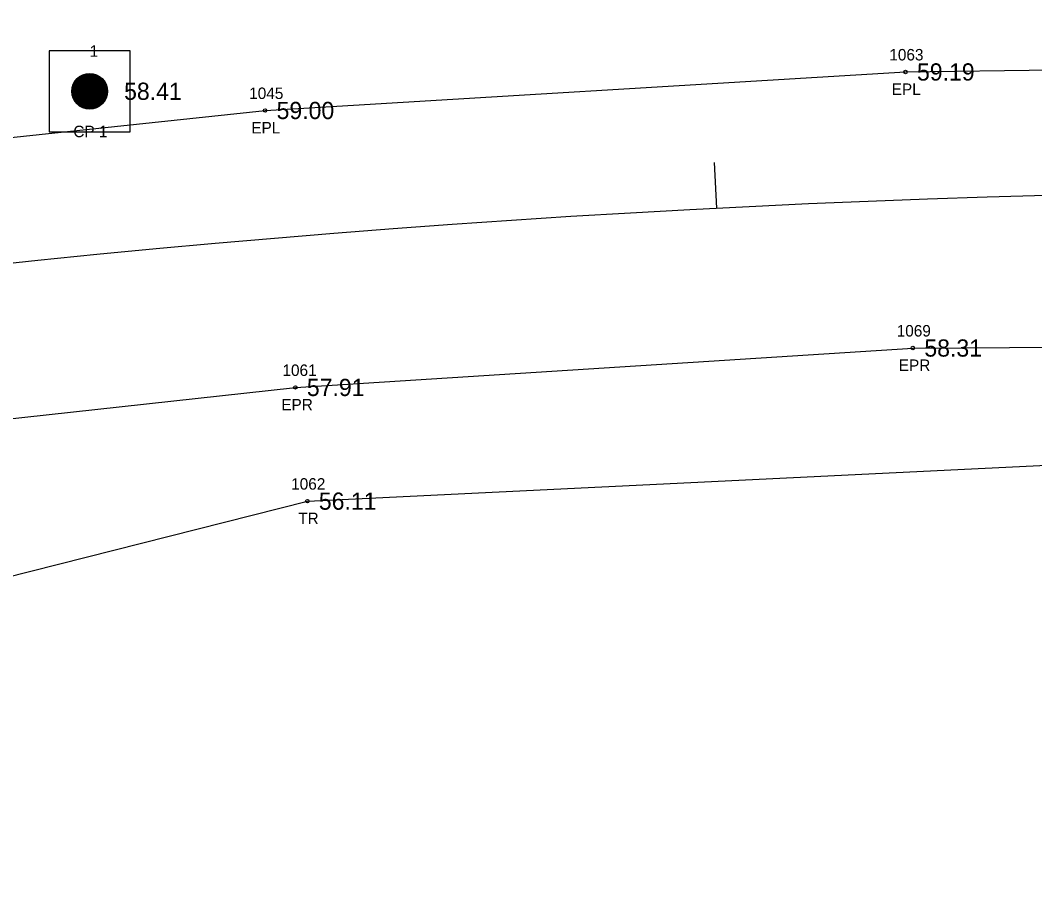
# Model space of a CAD drawing. Extents: x 2420113 to 2422887, y 845323 to 846653.
# Drawn here: x 2420530 to 2420618.3, y 845663.8 to 845739.4 of the extents above; entities that cross this region are included whole.
import ezdxf

# ---------------------------------------------------------------- set-up
doc = ezdxf.new("R2010")
doc.units = 0
for name, color, linetype in [('RD_EX_Road', 7, 'Continuous'), ('RD_EX_Road_txCode', 7, 'Continuous'), ('RD_EX_TX_Road_ELEV', 7, 'Continuous'), ('RD_EX_TX_VEG_ELEV', 7, 'Continuous'), ('RD_EX_VEG', 7, 'Continuous'), ('RD_EX_VEG_txCode', 7, 'Continuous'), ('RD_HC_Cl', 7, 'Continuous'), ('RD_HC_Data_Tic', 7, 'Continuous'), ('RD_HC_Survey', 7, 'Continuous'), ('RD_HC_Survey_ELEV', 7, 'Continuous'), ('RD_HC_Survey_txCode', 7, 'Continuous'), ('RD_SMD_Locator', 7, 'Continuous')]:
    doc.layers.add(name, color=color, linetype=linetype)

msp = doc.modelspace()

# ---------------------------------------------------------------- linework, layer by layer
at = {"layer": 'RD_EX_Road'}
for points in [[(2420388.282, 845680.385), (2420441.289, 845692.044), (2420492.621, 845700.703), (2420553.92, 845707.412), (2420607.692, 845710.846), (2420682.38, 845711.255), (2420749.444, 845707.273), (2420795.122, 845703.444), (2420900.283, 845693.42), (2421017.167, 845682.19), (2421113.896, 845672.969), (2421174.872, 845668.158), (2421234.589, 845666.133), (2421293.003, 845667.248), (2421351.244, 845671.501), (2421419.818, 845681.166), (2421463.191, 845688.629), (2421558.819, 845713.183), (2421614.573, 845730.452), (2421670.73, 845751.42), (2421735.61, 845780.497), (2421750.751, 845787.871), (2421744.667, 845798.217), (2421739.213, 845808.113)], [(2420376.352, 845701.929), (2420403.683, 845709.109), (2420436.454, 845715.41), (2420465.848, 845720.803), (2420487.585, 845724.764), (2420551.285, 845731.534), (2420607.051, 845734.891), (2420658.723, 845735.587), (2420682.859, 845735.472), (2420736.675, 845732.558), (2420795.395, 845727.646), (2420889.703, 845718.983), (2420911.08, 845716.872), (2420953.907, 845713.711), (2420998.338, 845708.254), (2421018.473, 845706.548), (2421116.022, 845696.98), (2421176.982, 845692.004), (2421235.853, 845690.144), (2421292.319, 845691.436), (2421350.221, 845695.49), (2421412.35, 845704.283)]]:
    msp.add_lwpolyline(points, dxfattribs=at)
at = {"layer": 'RD_EX_VEG'}
msp.add_lwpolyline([(2420391.438, 845659.631), (2420497.123, 845682.866), (2420554.964, 845697.51), (2420665.259, 845702.876), (2420735.635, 845697.654), (2420790.664, 845674.795), (2421018.223, 845655.053), (2421176.125, 845636.219), (2421296.761, 845636.574), (2421411.609, 845653.106), (2421415.242, 845569.551)], dxfattribs=at)
at = {"layer": 'RD_HC_Cl'}
msp.add_arc((2420649.068, 844578.355), 1146.148, 84.464761, 117.648099, dxfattribs=at)
at = {"layer": 'RD_HC_Data_Tic'}
msp.add_line((2420590.62, 845723.012), (2420590.416, 845727.007), dxfattribs=at)
at = {"layer": 'RD_HC_Survey'}
for p, q in [((2420534.794, 845732.234), (2420534.794, 845734.181)), ((2420534.844, 845732.175), (2420534.844, 845734.24)), ((2420534.894, 845732.121), (2420534.894, 845734.294)), ((2420534.944, 845732.072), (2420534.944, 845734.343)), ((2420534.994, 845732.027), (2420534.994, 845734.388)), ((2420535.044, 845731.986), (2420535.044, 845734.429)), ((2420535.094, 845731.949), (2420535.094, 845734.467)), ((2420535.144, 845731.914), (2420535.144, 845734.501)), ((2420535.194, 845731.882), (2420535.194, 845734.533)), ((2420535.244, 845731.853), (2420535.244, 845734.563)), ((2420535.294, 845731.826), (2420535.294, 845734.59)), ((2420535.344, 845731.801), (2420535.344, 845734.614)), ((2420535.394, 845731.778), (2420535.394, 845734.637)), ((2420535.444, 845731.758), (2420535.444, 845734.657)), ((2420535.494, 845731.74), (2420535.494, 845734.675)), ((2420535.544, 845731.723), (2420535.544, 845734.692)), ((2420535.594, 845731.709), (2420535.594, 845734.707)), ((2420535.644, 845731.696), (2420535.644, 845734.719)), ((2420535.694, 845731.685), (2420535.694, 845734.731)), ((2420535.744, 845731.675), (2420535.744, 845734.74)), ((2420535.794, 845731.668), (2420535.794, 845734.748)), ((2420535.844, 845731.661), (2420535.844, 845734.754)), ((2420535.894, 845731.657), (2420535.894, 845734.758)), ((2420535.944, 845731.654), (2420535.944, 845734.761)), ((2420535.994, 845731.653), (2420535.994, 845734.762)), ((2420536.044, 845731.653), (2420536.044, 845734.762)), ((2420536.094, 845731.656), (2420536.094, 845734.76)), ((2420536.144, 845731.659), (2420536.144, 845734.756)), ((2420536.194, 845731.664), (2420536.194, 845734.751)), ((2420536.244, 845731.671), (2420536.244, 845734.744)), ((2420536.294, 845731.68), (2420536.294, 845734.735)), ((2420536.344, 845731.69), (2420536.344, 845734.725)), ((2420536.394, 845731.702), (2420536.394, 845734.713)), ((2420536.444, 845731.716), (2420536.444, 845734.699)), ((2420536.494, 845731.732), (2420536.494, 845734.684)), ((2420536.544, 845731.749), (2420536.544, 845734.666)), ((2420536.594, 845731.769), (2420536.594, 845734.647)), ((2420536.644, 845731.79), (2420536.644, 845734.625)), ((2420536.694, 845731.814), (2420536.694, 845734.602)), ((2420536.744, 845731.839), (2420536.744, 845734.576)), ((2420536.794, 845731.868), (2420536.794, 845734.548)), ((2420536.844, 845731.898), (2420536.844, 845734.517)), ((2420536.894, 845731.932), (2420536.894, 845734.484)), ((2420536.944, 845731.968), (2420536.944, 845734.447)), ((2420536.994, 845732.007), (2420536.994, 845734.408)), ((2420537.044, 845732.05), (2420537.044, 845734.365)), ((2420537.094, 845732.097), (2420537.094, 845734.318)), ((2420537.144, 845732.149), (2420537.144, 845734.267)), ((2420537.194, 845732.205), (2420537.194, 845734.21)), ((2420537.244, 845732.267), (2420537.244, 845734.148)), ((2420534.494, 845732.846), (2420534.494, 845733.569)), ((2420534.544, 845732.679), (2420534.544, 845733.736)), ((2420534.594, 845732.557), (2420534.594, 845733.858)), ((2420534.644, 845732.458), (2420534.644, 845733.957)), ((2420534.694, 845732.374), (2420534.694, 845734.042)), ((2420534.744, 845732.3), (2420534.744, 845734.116)), ((2420537.294, 845732.337), (2420537.294, 845734.078)), ((2420537.344, 845732.416), (2420537.344, 845733.999)), ((2420537.394, 845732.508), (2420537.394, 845733.908)), ((2420537.444, 845732.617), (2420537.444, 845733.798)), ((2420537.494, 845732.758), (2420537.494, 845733.657)), ((2420537.544, 845732.982), (2420537.544, 845733.433))]:
    msp.add_line(p, q, dxfattribs=at)
msp.add_lwpolyline([(2420539.541, 845736.743), (2420532.47, 845736.743), (2420532.47, 845729.672), (2420539.541, 845729.672)], close=True, dxfattribs=at)
msp.add_circle((2420536.006, 845733.208), 1.555, dxfattribs=at)
at = {"layer": 'RD_SMD_Locator'}
for centre in [(2420607.051, 845734.891), (2420536.006, 845733.208), (2420551.285, 845731.534), (2420607.692, 845710.846), (2420553.92, 845707.412), (2420554.964, 845697.51)]:
    msp.add_circle(centre, 0.15, dxfattribs=at)

# ---------------------------------------------------------------- texts
at = {"layer": 'RD_EX_Road_txCode'}
for s, p in [('1063', (2420605.641, 845735.891)), ('1045', (2420549.899, 845732.534)), ('EPL', (2420605.846, 845732.891)), ('EPL', (2420550.081, 845729.534)), ('1069', (2420606.283, 845711.846)), ('1061', (2420552.794, 845708.412)), ('EPR', (2420606.464, 845708.846)), ('EPR', (2420552.692, 845705.412))]:
    msp.add_text(s, height=1, dxfattribs=at).set_placement(p)
at = {"layer": 'RD_EX_TX_Road_ELEV'}
for s, p in [('59.19', (2420608.051, 845734.141)), ('59.00', (2420552.285, 845730.784)), ('58.31', (2420608.692, 845710.096)), ('57.91', (2420554.92, 845706.662))]:
    msp.add_text(s, height=1.5, dxfattribs=at).set_placement(p)
at = {"layer": 'RD_EX_TX_VEG_ELEV'}
msp.add_text('56.11', height=1.5, dxfattribs=at).set_placement((2420555.964, 845696.76))
at = {"layer": 'RD_EX_VEG_txCode'}
for s, p in [('1062', (2420553.554, 845698.51)), ('TR', (2420554.168, 845695.51))]:
    msp.add_text(s, height=1, dxfattribs=at).set_placement(p)
at = {"layer": 'RD_HC_Survey_ELEV'}
msp.add_text('58.41', height=1.5, dxfattribs=at).set_placement((2420539.006, 845732.458))
at = {"layer": 'RD_HC_Survey_txCode'}
for s, p in [('1', (2420536.006, 845736.208)), ('CP 1', (2420534.588, 845729.208))]:
    msp.add_text(s, height=1, dxfattribs=at).set_placement(p)

doc.saveas('drawing.dxf')
